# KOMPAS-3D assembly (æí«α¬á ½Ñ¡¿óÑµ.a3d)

Referenced files in D:\МОДЕЛЬ ТАНКА Т90\ДЕТАЛИ\ХОДОВАЯ\Ленивец с эксцентриком\: ленивец1.m3d
Referenced files in D:\МОДЕЛЬ ТАНКА Т90\ДЕТАЛИ\ХОДОВАЯ\Каток опорный с балансиром\: втулка соеденения катков.m3d, шпилька соеденения катков.m3d
Referenced files in D:\МОДЕЛЬ ТАНКА Т90\ДЕТАЛИ\ОБЩИЕ ДЕТАЛИ\: подшипник 13-5-4.m3d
